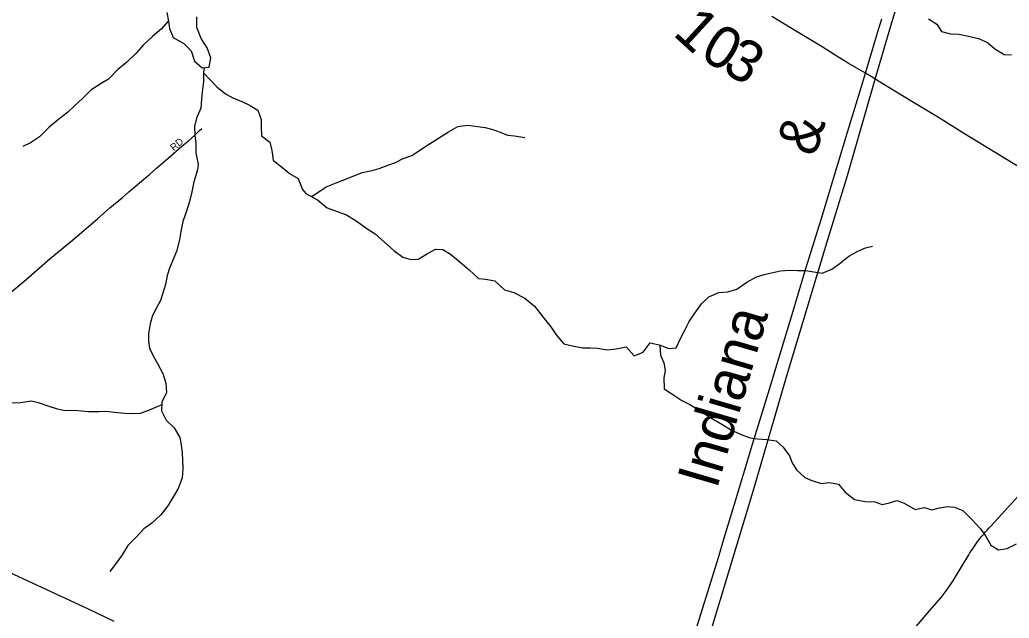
# Model space of a CAD drawing. Extents: x 1442749 to 1756758, y 235267 to 677782.
# Drawn here: x 1577781 to 1584856, y 500562 to 504843 of the extents above; entities that cross this region are included whole.
import ezdxf

# ---------------------------------------------------------------- set-up
doc = ezdxf.new("R2010")
doc.units = 0
for name, color, linetype in [('GM_X_County_Road', 7, 'Continuous'), ('GM_X_Major_Lake', 7, 'Continuous'), ('GM_X_Minor_River', 7, 'Continuous'), ('GM_X_Rail_Line', 7, 'Continuous'), ('GM_X_Rail_Line_Text', 7, 'Continuous'), ('GM_X_State_Route', 7, 'Continuous'), ('GM_X_Township_Road', 7, 'Continuous'), ('GM_X_Township_Road_Text', 7, 'Continuous'), ('GM_X_Township_Subdivision', 7, 'Continuous'), ('GM_X_Township_Subdivision_Text', 7, 'Continuous'), ('GM_X_US_Route', 7, 'Continuous')]:
    doc.layers.add(name, color=color, linetype=linetype)

msp = doc.modelspace()

# ---------------------------------------------------------------- linework, layer by layer
at = {"layer": 'GM_X_County_Road'}
msp.add_lwpolyline([(1584080.3, 500374.6), (1584301.1, 500630.3), (1584368.7, 500710.5), (1584405, 500756.8), (1584422.5, 500781.1), (1584439.3, 500804.5), (1584453.2, 500826), (1584465.9, 500845.6), (1584566.4, 501014.2), (1584575.7, 501028.5), (1584585, 501042.9), (1584595.1, 501058.4), (1584602.1, 501069.2), (1584613, 501084.6), (1584622.7, 501098.4), (1584632.5, 501112.2), (1584644.2, 501127.3), (1584658.7, 501146), (1584674.2, 501164), (1584686.9, 501178.7), (1584697.5, 501190.9), (1584710.5, 501205.4), (1584726.3, 501222.9), (1584776.5, 501278.7), (1584922.5, 501438.3)], dxfattribs=at)
at = {"layer": 'GM_X_Major_Lake'}
msp.add_lwpolyline([(1578833.4, 504894.4), (1578843.6, 504832), (1578852.2, 504781.7), (1578878.3, 504716.9), (1578955.1, 504672.7), (1579005.6, 504621.2), (1579031.5, 504546.4), (1579086.1, 504498.8), (1579136.2, 504503.4), (1579148.2, 504571.2), (1579122.2, 504642), (1579078.1, 504709.4), (1579046.4, 504788.4), (1579046.6, 504864.5)], dxfattribs=at)
at = {"layer": 'GM_X_Minor_River'}
for points in [[(1578843.5, 504833), (1578794.7, 504778.3), (1578729.6, 504723.5), (1578666.4, 504664.7), (1578613.1, 504603.6), (1578545.8, 504540.9), (1578482.7, 504488), (1578415.2, 504417.3), (1578362.6, 504388.2), (1578289.6, 504339.6), (1578230.4, 504280.7), (1578173.3, 504227.7), (1578122.3, 504180.7), (1578061.3, 504131.8), (1577992.1, 504075.1), (1577922.7, 504006.3), (1577857.8, 503961.5), (1577803.3, 503936.6)], [(1584278.1, 504849.5), (1584339.8, 504810.6), (1584371.3, 504760.1), (1584437.2, 504743.3), (1584495.3, 504740.6), (1584565.3, 504725.8), (1584637.2, 504708.9), (1584701, 504680.1), (1584752.6, 504635.4), (1584820.3, 504594.5), (1584872.3, 504591.9)], [(1579099.5, 504500.1), (1579094.4, 504467.9), (1579095, 504399.8), (1579087.9, 504345.8), (1579080.4, 504273.9), (1579075.1, 504209.9), (1579045.6, 504140.3), (1579030.4, 504078.5), (1579033, 504012.4), (1579040, 503962.2), (1579040.5, 503892), (1579055.8, 503808.6), (1579051.1, 503769.5)], [(1579094.4, 504463.8), (1579190.3, 504363.8), (1579253.2, 504312.5), (1579310.6, 504283.3), (1579364.2, 504260.2), (1579427.6, 504230.9), (1579482.9, 504195.8), (1579507.5, 504129.2), (1579506.4, 504077.1), (1579509.1, 504013), (1579570.2, 503967.7), (1579582.9, 503907.3), (1579593.5, 503839), (1579691.3, 503759.2)], [(1580230.4, 503751.2), (1580300.7, 503765.9), (1580351, 503779.3), (1580409.4, 503800.7), (1580471.8, 503824.1), (1580522.2, 503849.6), (1580584.6, 503872.9), (1580635.1, 503906.4), (1580703.8, 503949.8), (1580774.5, 503997.1), (1580847.2, 504040.4), (1580913.8, 504079.7), (1580982, 504089), (1581110.1, 504071.5), (1581164.1, 504058.8), (1581215.9, 504038.2), (1581269.8, 504017.5), (1581319.9, 504012.9), (1581391.9, 504000)], [(1579051.1, 503769.5), (1579025.8, 503684.8), (1579012.7, 503612.8), (1578993.7, 503542.9), (1578972.6, 503473), (1578947.6, 503399.2), (1578932.5, 503327.2), (1578923.7, 503271.2), (1578904.5, 503191.3), (1578883.7, 503139.5), (1578852.6, 503065.8), (1578835.8, 503013.9), (1578822.9, 502949.9), (1578804, 502888), (1578787.2, 502834.1), (1578758.4, 502782.4), (1578729.6, 502726.7), (1578712.7, 502666.8), (1578701.6, 502596.8), (1578700.9, 502546.7), (1578708.2, 502494.5), (1578731.5, 502444), (1578768.6, 502379.4), (1578803.6, 502312.8), (1578826.7, 502244.3), (1578829.7, 502176.1), (1578796.6, 502108.4), (1578795.7, 502044.3), (1578828.8, 501979.7), (1578884.1, 501924.8), (1578925.1, 501854.1), (1578934.3, 501801.8), (1578941.5, 501741.6), (1578944.7, 501691.5), (1578947.9, 501633.3), (1578942.9, 501565.2), (1578913.8, 501489.4), (1578883, 501437.7), (1578839.9, 501366.1), (1578790.9, 501300.7), (1578726, 501241.4), (1578667.4, 501202.1), (1578610.4, 501138.8), (1578553.5, 501081.4), (1578514.5, 501015.8), (1578477.7, 500964.2), (1578424.6, 500894.8)], [(1579691.3, 503759.2), (1579709.3, 503743.6), (1579772.8, 503706.7), (1579802.4, 503629.8), (1579827.5, 503600.8)], [(1579870, 503577.8), (1579972.4, 503647), (1580042.9, 503676.2), (1580129.6, 503709.1), (1580230.4, 503751.2)], [(1579827.5, 503600.8), (1579911, 503555.6), (1579980.3, 503496.6), (1580050.2, 503471.6), (1580118.1, 503448.7), (1580185.7, 503403.7), (1580269.1, 503344.5), (1580322.8, 503311.8), (1580390.2, 503252.8), (1580455.6, 503191.8), (1580521.1, 503144.9), (1580577, 503128.1), (1580629.2, 503131.4), (1580689.9, 503166.7), (1580754.5, 503202), (1580806.6, 503199.3), (1580860.3, 503166.5), (1580929.7, 503109.5), (1580995.2, 503054.5), (1581060.5, 502991.6), (1581112.6, 502986.9), (1581178.6, 502976), (1581248, 502911), (1581313.9, 502892.1), (1581393.5, 502851), (1581461, 502794), (1581522.1, 502719), (1581579.3, 502646.1), (1581616.6, 502589.5), (1581671.9, 502524.7), (1581743.9, 502507.7), (1581807.9, 502496.9), (1581860.1, 502496.2), (1581912.2, 502493.5), (1581982.2, 502482.6), (1582046.5, 502487.8), (1582116.8, 502502.9), (1582174.1, 502438), (1582238.7, 502465.2), (1582287.7, 502530.7), (1582353.7, 502517.9), (1582423.5, 502490.9), (1582473.7, 502496.3), (1582504.7, 502562), (1582535.5, 502617.7), (1582568.5, 502683.4), (1582607.4, 502745.1), (1582656.5, 502810.6), (1582707.3, 502860), (1582779.9, 502891.1), (1582844.1, 502896.3), (1582908.6, 502915.5), (1582979.4, 502964.7), (1583048.1, 503003.9), (1583104.5, 503021.2), (1583164.9, 503034.5), (1583221.2, 503045.8), (1583289.5, 503052.9), (1583341.6, 503050.2), (1583401.7, 503049.5), (1583459.7, 503038.7), (1583519.8, 503029.9), (1583588.4, 503059.1), (1583639, 503094.5), (1583709.9, 503151.7), (1583772.6, 503187), (1583829.1, 503212.3), (1583879.4, 503223.7)], [(1582358.1, 502516.2), (1582362.7, 502443.6), (1582386.1, 502389.2), (1582397.3, 502332.9), (1582386.6, 502280.9), (1582389.6, 502202.7), (1582443.2, 502168), (1582514.8, 502118.9), (1582572.6, 502090.1), (1582640.2, 502051.2), (1582715.7, 502000.1), (1582801.3, 501948.9), (1582870.9, 501907.9), (1582952.6, 501870.8), (1583004.5, 501852), (1583056.6, 501845.3), (1583122.7, 501840.5), (1583188.7, 501829.6), (1583240.3, 501784.8), (1583285.6, 501724.1), (1583305, 501673.8), (1583334.4, 501623.3), (1583393.8, 501568.4), (1583445.7, 501547.7), (1583511.5, 501524.8), (1583571.8, 501532), (1583635.8, 501521.2), (1583683.2, 501464.5), (1583750.7, 501411.5), (1583826.7, 501396.5), (1583894.8, 501393.6), (1583948.7, 501374.8), (1584001, 501388.2), (1584053.4, 501403.5), (1584105.3, 501384.8), (1584182.9, 501339.7), (1584251.2, 501352.9), (1584303.2, 501338.2), (1584357.5, 501351.5), (1584413.8, 501360.8), (1584465.9, 501356.1), (1584523.7, 501331.3), (1584589, 501268.3), (1584650.3, 501201.4), (1584687.7, 501150.8), (1584724.9, 501084.2), (1584778.6, 501051.4), (1584840.9, 501060.6), (1584907.6, 501093.8)], [(1578796.4, 502088.3), (1578701.7, 502047.5), (1578641.3, 502026.3), (1578583.2, 502025.1), (1578529.2, 502025.8), (1578459.2, 502032.8), (1578397.2, 502039.7), (1578347.2, 502038.3), (1578273.1, 502039.4), (1578173.2, 502048.7), (1578107, 502045.6), (1578051.2, 502058.4), (1577983.4, 502079.4), (1577915.7, 502102.4), (1577863.8, 502115.1), (1577787.5, 502102.1), (1577733.5, 502100.8), (1577659.4, 502101.8), (1577585.2, 502094.8), (1577531, 502079.5), (1577450.8, 502076.6), (1577378.9, 502083.6), (1577310.9, 502092.6)]]:
    msp.add_lwpolyline(points, dxfattribs=at)
at = {"layer": 'GM_X_Rail_Line'}
msp.add_lwpolyline([(1582585.2, 500008.7), (1583033.7, 501494.5), (1583263.8, 502288.3), (1583558.1, 503270.9), (1583699.7, 503730.1), (1583898.7, 504417.6), (1584010.9, 504800.7), (1584087.4, 505062.4)], dxfattribs=at)
at = {"layer": 'GM_X_State_Route'}
msp.add_lwpolyline([(1577669.8, 500908.8), (1577904.6, 500799.1), (1578270.5, 500628.8), (1578454.4, 500541.8)], dxfattribs=at)
at = {"layer": 'GM_X_Township_Road'}
for points in [[(1583828.5, 504461.7), (1583704.9, 504533.2), (1583611.9, 504588.8), (1583517.6, 504648.4), (1583411.7, 504713.9), (1583305.4, 504778.8), (1583159.2, 504866.6)], [(1586175, 503025.9), (1586150, 503042.1), (1586116.9, 503063.6), (1585913.5, 503190.2), (1585537.5, 503418.2), (1585363.1, 503522.9), (1585242.7, 503596.4), (1585038, 503720.8), (1584536.5, 504026.4), (1584350.1, 504143.1), (1584159.4, 504258.9), (1583929.9, 504398.8), (1583868.6, 504436.9), (1583828.5, 504461.7)]]:
    msp.add_lwpolyline(points, dxfattribs=at)
at = {"layer": 'GM_X_Township_Subdivision'}
for points in [[(1578561.8, 503612.4), (1578636.6, 503676.1), (1578708.4, 503737.3), (1578759, 503781.3), (1578842.2, 503853.2), (1578941, 503938.8), (1578986.7, 503978), (1579032.3, 504018), (1579067.4, 504050.6), (1579082.1, 504065.3)], [(1577334.7, 502578.6), (1577351.6, 502585.1), (1577363.1, 502590.5), (1577371.3, 502595), (1577380.4, 502601.4), (1577393.2, 502611.2), (1577443, 502651.7), (1577540.6, 502740.1), (1577696.9, 502876.3), (1577826.2, 502984.9), (1577998.4, 503135), (1578144.5, 503254.2), (1578336.3, 503419), (1578425.2, 503496.5), (1578515, 503572.4), (1578561.8, 503612.4)]]:
    msp.add_lwpolyline(points, dxfattribs=at)
at = {"layer": 'GM_X_US_Route'}
msp.add_lwpolyline([(1582618.9, 500483), (1582698.5, 500743.4), (1582777.4, 500997.1), (1582821.1, 501145), (1582889.1, 501371.1), (1583023.1, 501813.8), (1583150.7, 502231.1), (1583210.1, 502429), (1583300.8, 502727.2), (1583393.3, 503031.7), (1583520.6, 503445.6), (1583560.7, 503580.9), (1583699.5, 504039.3), (1583807.1, 504390.6), (1583828.5, 504461.7), (1583908.3, 504726.7), (1583928.9, 504796.6), (1583937.3, 504825), (1583944.6, 504849.5)], dxfattribs=at)

# ---------------------------------------------------------------- texts
at = {"layer": 'GM_X_Rail_Line_Text'}
for s, rotation, p in [('&', 73.68494, (1583470.2, 503857)), ('Indiana', 73.65779, (1582765.3, 501478.6))]:
    msp.add_text(s, height=299, rotation=rotation, dxfattribs=at).set_placement(p)
at = {"layer": 'GM_X_Township_Road_Text'}
for s, rotation, p in [('1', 317.5346, (1582443.7, 504739.1)), ('0', 329.32169, (1582634, 504574.2)), ('3', 328.94789, (1582792.5, 504480.2))]:
    msp.add_text(s, height=300, rotation=rotation, dxfattribs=at).set_placement(p)
at = {"layer": 'GM_X_Township_Subdivision_Text'}
msp.add_text('RD', height=50, rotation=40.60386, dxfattribs=at).set_placement((1578883.1, 503901.9))

doc.saveas('drawing.dxf')
